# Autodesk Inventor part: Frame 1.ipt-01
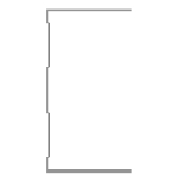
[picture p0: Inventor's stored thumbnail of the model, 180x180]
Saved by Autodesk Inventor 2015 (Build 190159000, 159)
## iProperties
_CCFamilyMember: 1
_CCFamilyDisplayName: Kévin - Kévin Novo
_FrameMemberDoc: Frame Member File
_Version: 15.0.0
_GetPNFromCC: 1
Created: 2015-04
Part Number: Frame 1.ipt-01
Material: Aluminum 6061
Description: Kévin Novo
Document SubType Name: Modeling
Standard: Kevin
Designer: suporte
Standards Organization: Kevin
Language: en-US
Size Designation: (Unnamed 1)
Categories: <MemberInstance><Categories><Category DisplayName="Structural Shapes" InternalName="089c4875-fa83-4c05-b084-43b9cc11f5ed" Mnemonic="GRDR"><CategoryParameter Dis
Density: 2.7 g/cm^3
Appearance: Aluminum - Flat
IsCustomPart: 1
G_L: 1248,573 mm
G_W: 50,000 mm
G_H: 75,000 mm
+A62EFF7C-91EB-4CC1-A7B9-854253522743+CUTDETAIL1: Cut
+4D809EA7-788C-49E5-BB68-DE73CC06A589+CUTDETAIL2: Cut
Author: suporte
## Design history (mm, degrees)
node "Start Plane"
node "End Plane"
sketch "Sketch"
  geometry: L1 (24.7, 37.5)-(24.7, 36.9); L2 (24.7, 36.9)-(-24.7, 36.9); L3 (-24.7, -36.9)-(24.7, -36.9); L4 (24.7, -36.9)-(24.7, -37.5); L5 (24.7, -37.5)-(-25.3, -37.5); L6 (-25.3, 37.5)-(24.7, 37.5); L7 (-24.7, 36.9)-(-24.7, 31.9); L8 (-24.7, 31.9)-(-23.3, 30.5); L9 (-23.3, 30.5)-(-23.3, 10.934); L10 (-23.3, 10.934)-(-24.7, 9.534); L11 (-24.7, 9.534)-(-24.7, -9.534); L12 (-24.7, -9.534)-(-23.3, -10.934); L13 (-23.3, -10.934)-(-23.3, -30.5); L14 (-23.3, -30.5)-(-24.7, -31.9); L15 (-24.7, -31.9)-(-24.7, -36.9); L16 (-25.3, -37.5)-(-25.3, -31.651); L17 (-25.3, -31.651)-(-23.9, -30.251); L18 (-23.9, -30.251)-(-23.9, -11.183); L19 (-23.9, -11.183)-(-25.3, -9.783); L20 (-25.3, -9.783)-(-25.3, 9.783); L21 (-25.3, 9.783)-(-23.9, 11.183); L22 (-23.9, 11.183)-(-23.9, 30.251); L23 (-23.9, 30.251)-(-25.3, 31.651); L24 (-25.3, 31.651)-(-25.3, 37.5); L25 (-25.3, 0)-(30.37, 0); 3 further points
  constraints: 50 end point, 10 point on line, 9 parallel, 5 perpendicular, 4 equal length, 3 midpoint, 3 vertical, 2 vertical alignment, 1 collinear, 1 horizontal, 1 horizontal alignment
  dimensions: "d3" = 0.6 distance of L1.start L1.end (= d6); "d5" = 75 distance between parallel lines of L5 L6; "d6" = 0.6 distance between parallel lines of L24 L7 (= d8); "d7" = 0.6 distance between parallel lines of L8 L23 (= d8); "d8" = 0.6 distance between parallel lines of L22 L9 (= d12); "Espessura" = 0.6 distance between parallel lines of L17 L14; "d10" = 0.6 distance between parallel lines of L13 L18 (= Espessura); "d11" = 0.6 distance between parallel lines of L12 L19 (= Espessura); "d12" = 0.6 distance between parallel lines of L21 L10 (= d11); "d13" = 5 distance of L2.end L7.end; "d15" = 135 deg angle of L9 L8; "d16" = 2 distance between parallel lines of L24 L9; "d17" = 50 distance of L6.start L1.start
extrude "Body" join sketch "Sketch" stored distance "d24" = 0.13; taper "d25" = 0 deg
node "Driven Length"
  sketch "Sketch10"
    geometry: L1 (0, 0)-(10, 0) reference
    constraints: 2 end point, 1 horizontal
  workplane "Work Plane7"
  sketch "Sketch11"
    geometry: L1 (-2, -87.5)-(12, -87.5) reference; L2 (-2, 1161.073)-(12, 1161.073) reference
    dimensions: "d27" = 1248.57326 distance between parallel lines of L1 L2 (derived)
workplane "Work Plane8"
split "Split1"
workplane "Work Plane9"
split "Split2"
body "Solid1"
other parameters: "tamanho" = 1093.43652, "G_OFFSET_START" = 87.5 [user parameter; used in 1 equation term], "G_OFFSET_END" = 67.63674 [user parameter; used in 1 equation term], "d22" = -87.5 (= -G_OFFSET_START), "d23" = 1161.07326 (= tamanho + G_OFFSET_END), "G_L" = 1248.57326 (= d27) [user parameter], "d34" = 90 deg
